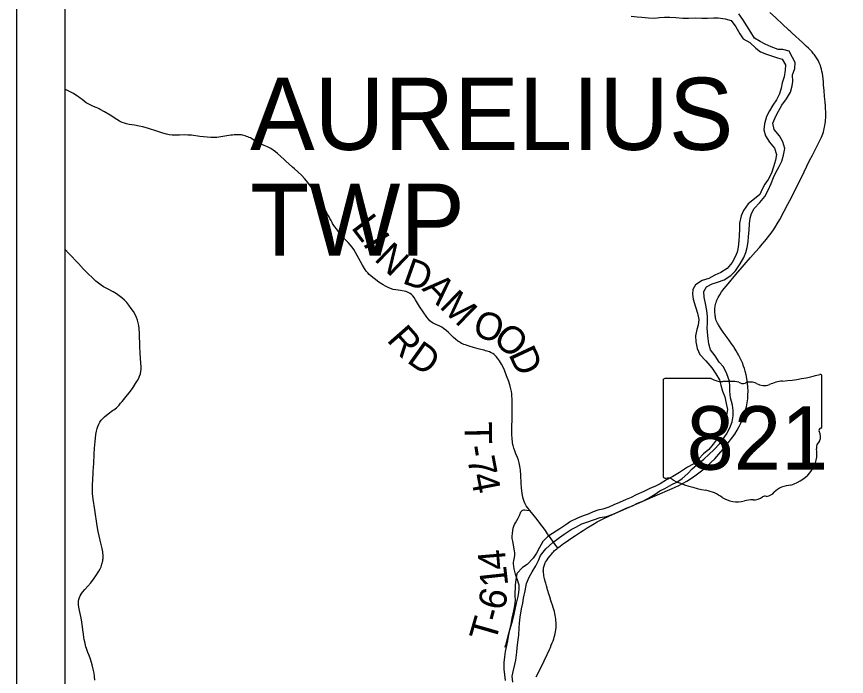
# Model space of a CAD drawing. Extents: x -10 to 158, y 8 to 33.
# Drawn here: x 126.004 to 127.727, y 27.363 to 28.734 of the extents above; entities that cross this region are included whole.
import ezdxf

# ---------------------------------------------------------------- set-up
doc = ezdxf.new("R2010")
doc.units = 0
for name, color, linetype in [('GM_X_Major_River', 7, 'Continuous'), ('GM_X_State_Location', 7, 'Continuous'), ('GM_X_State_Route', 7, 'Continuous'), ('GM_X_State_Shield', 7, 'Continuous'), ('GM_X_Township_Road', 7, 'Continuous'), ('GM_X_Township_Road_Text', 7, 'Continuous'), ('GM_X_Township_Text', 7, 'Continuous'), ('SH_Data', 7, 'Continuous')]:
    doc.layers.add(name, color=color, linetype=linetype)

msp = doc.modelspace()

# ---------------------------------------------------------------- linework, layer by layer
at = {"layer": 'GM_X_Major_River'}
for points in [[(127.2824, 27.7179), (127.293, 27.7233), (127.3043, 27.7277), (127.3156, 27.7339), (127.3295, 27.742), (127.3396, 27.7486), (127.3498, 27.7537), (127.3641, 27.7619), (127.375, 27.7669), (127.3859, 27.7743), (127.3979, 27.7851), (127.4069, 27.7947), (127.4196, 27.8055), (127.4305, 27.8147), (127.4413, 27.8243), (127.4526, 27.8347), (127.463, 27.8466), (127.4712, 27.857), (127.4779, 27.8666), (127.4846, 27.8799), (127.4893, 27.8921), (127.4914, 27.905), (127.4916, 27.916), (127.4904, 27.9267), (127.486, 27.9418), (127.485, 27.9562), (127.4845, 27.966), (127.484, 27.977), (127.4789, 27.9917), (127.4718, 28.0068), (127.4626, 28.0165), (127.4545, 28.0293), (127.4448, 28.0421), (127.4409, 28.0542), (127.4396, 28.0655), (127.4383, 28.0784), (127.4377, 28.0879), (127.4384, 28.0974), (127.4382, 28.111), (127.4369, 28.1239), (127.4344, 28.1379), (127.4316, 28.1511), (127.431, 28.1629), (127.4362, 28.1728), (127.4483, 28.179), (127.4592, 28.1822), (127.4732, 28.187), (127.4871, 28.1963), (127.4968, 28.2063), (127.5065, 28.2208), (127.5139, 28.2334), (127.5183, 28.2441), (127.5208, 28.2544), (127.5229, 28.2665), (127.5239, 28.2772), (127.5248, 28.2908), (127.5254, 28.3037), (127.5268, 28.3155), (127.5297, 28.325), (127.5356, 28.3357), (127.5472, 28.348), (127.5576, 28.3603), (127.5643, 28.3737), (127.5709, 28.3874), (127.5753, 28.3996), (127.5805, 28.4103), (127.5871, 28.4225), (127.5927, 28.4336), (127.5963, 28.4462), (127.5991, 28.4602), (127.5951, 28.4742), (127.5881, 28.4866), (127.5766, 28.4994), (127.5741, 28.513), (127.5804, 28.5271), (127.5856, 28.5378), (127.5926, 28.55), (127.6026, 28.5634), (127.6108, 28.5772), (127.614, 28.5901), (127.6158, 28.5996), (127.6149, 28.6133), (127.62, 28.6262), (127.6206, 28.6391), (127.6151, 28.6493), (127.6077, 28.6625), (127.5948, 28.6657), (127.5853, 28.6656), (127.5708, 28.6711), (127.5579, 28.677), (127.5479, 28.6822), (127.5357, 28.6896), (127.5283, 28.7016), (127.5202, 28.7151), (127.5121, 28.7279), (127.5036, 28.74)], [(127.4138, 28.7319), (127.4267, 28.7306), (127.4385, 28.7307), (127.451, 28.7317), (127.4608, 28.7318), (127.4749, 28.7293), (127.4878, 28.7257), (127.4971, 28.7129), (127.5056, 28.6986), (127.5126, 28.6877), (127.526, 28.68), (127.5387, 28.6684), (127.5486, 28.6609), (127.5612, 28.6558), (127.5711, 28.6525), (127.5837, 28.6485), (127.5932, 28.646), (127.6005, 28.6339), (127.5999, 28.6226), (127.5975, 28.6092), (127.5938, 28.5967), (127.5917, 28.5857), (127.5877, 28.5738), (127.5814, 28.5612), (127.574, 28.5501), (127.567, 28.5383), (127.5607, 28.5265), (127.5567, 28.5112), (127.5554, 28.4991), (127.5586, 28.4862), (127.5671, 28.4731), (127.5775, 28.4607), (127.5815, 28.4475), (127.5797, 28.4357), (127.5754, 28.422), (127.571, 28.409), (127.5644, 28.3957), (127.5573, 28.3861), (127.5514, 28.3739), (127.5473, 28.3643), (127.5327, 28.3528), (127.5226, 28.345), (127.5129, 28.3312), (127.5081, 28.3202), (127.5049, 28.3053), (127.5051, 28.2928), (127.5045, 28.2796), (127.5035, 28.2682), (127.5022, 28.2549), (127.4997, 28.2446), (127.496, 28.2351), (127.4897, 28.2232), (127.4793, 28.2106), (127.4661, 28.2024), (127.4537, 28.1969), (127.4413, 28.1903), (127.4273, 28.1856), (127.4138, 28.1771), (127.4079, 28.1671), (127.4072, 28.1573), (127.4089, 28.147), (127.4136, 28.1315), (127.4176, 28.118), (127.4201, 28.1047), (127.4187, 28.0933), (127.4162, 28.0838), (127.4133, 28.0709), (127.4139, 28.0584), (127.4171, 28.0447), (127.4226, 28.0323), (127.4353, 28.0188), (127.4476, 28.0042), (127.4557, 27.9918), (127.4631, 27.9794), (127.4659, 27.9684), (127.4695, 27.9563), (127.4742, 27.9439), (127.477, 27.9303), (127.4799, 27.9182), (127.4781, 27.9056), (127.4726, 27.893), (127.4664, 27.8789), (127.4605, 27.8637), (127.4561, 27.8541), (127.4501, 27.8458), (127.4413, 27.8348), (127.4303, 27.8256), (127.42, 27.8146), (127.4086, 27.8046), (127.3966, 27.7979), (127.3804, 27.7867), (127.3665, 27.779), (127.3533, 27.7716), (127.3402, 27.7638), (127.3304, 27.7587), (127.3187, 27.7537), (127.3059, 27.7478), (127.2901, 27.7404), (127.2799, 27.7353), (127.2693, 27.731), (127.2558, 27.7244)], [(127.2796, 28.735), (127.2925, 28.7337), (127.302, 28.7331), (127.3156, 28.7317), (127.3289, 28.7311), (127.3388, 28.732), (127.349, 28.7329), (127.3604, 28.7327), (127.3729, 28.7321), (127.3873, 28.7312), (127.3987, 28.7309), (127.4138, 28.7319)], [(127.2558, 27.7244), (127.2441, 27.72), (127.2335, 27.7153), (127.2211, 27.711), (127.2109, 27.709), (127.2007, 27.7054), (127.1909, 27.7007), (127.18, 27.6972), (127.1686, 27.6925), (127.1543, 27.6851), (127.1442, 27.6785), (127.1318, 27.67), (127.1168, 27.6603), (127.107, 27.6544), (127.0965, 27.6437), (127.0899, 27.6315), (127.0832, 27.6192), (127.0761, 27.6093), (127.0642, 27.5958), (127.0544, 27.5896), (127.0428, 27.577), (127.0407, 27.564), (127.0393, 27.5538), (127.0381, 27.531), (127.039, 27.5208), (127.038, 27.5109), (127.0355, 27.4999), (127.0319, 27.4847), (127.0302, 27.4721), (127.0274, 27.4599), (127.0245, 27.4466), (127.0231, 27.4371), (127.021, 27.4276), (127.0181, 27.4151), (127.0167, 27.4044), (127.0154, 27.3923), (127.0156, 27.3786), (127.0185, 27.3548)], [(127.0341, 27.3512), (127.0328, 27.3641), (127.0357, 27.3762), (127.0386, 27.388), (127.0403, 27.3975), (127.0428, 27.4135), (127.043, 27.423), (127.0444, 27.4348), (127.0465, 27.4488), (127.0474, 27.464), (127.048, 27.4739), (127.0497, 27.4868), (127.0522, 27.5039), (127.0547, 27.5157), (127.0564, 27.5263), (127.06, 27.5412), (127.0628, 27.5564), (127.0683, 27.5697), (127.0742, 27.5804), (127.082, 27.5934), (127.0872, 27.6041), (127.0916, 27.6144), (127.1028, 27.6286), (127.1174, 27.6417), (127.1309, 27.6517), (127.1407, 27.6587), (127.1553, 27.6684), (127.1651, 27.6738), (127.1772, 27.6801), (127.1877, 27.684), (127.2017, 27.6884), (127.2156, 27.6935), (127.2285, 27.6955), (127.2428, 27.7003), (127.2564, 27.7065), (127.2696, 27.7132), (127.2824, 27.7179)]]:
    msp.add_lwpolyline(points, dxfattribs=at)
at = {"layer": 'GM_X_State_Route'}
for points in [[(127.6133, 28.7005), (127.6098, 28.7037), (127.608, 28.7053), (127.6053, 28.7078), (127.5952, 28.7171), (127.5795, 28.732), (127.5676, 28.7429)], [(127.0828, 27.3622), (127.093, 27.3828), (127.1055, 27.4086), (127.1103, 27.4193), (127.1123, 27.4238), (127.114, 27.428), (127.1162, 27.4332), (127.1178, 27.4374), (127.1191, 27.4414), (127.1202, 27.445), (127.1212, 27.4488), (127.122, 27.4523), (127.1227, 27.4561), (127.1233, 27.4601), (127.1239, 27.4653), (127.1241, 27.4703), (127.124, 27.4753), (127.1238, 27.4787), (127.1235, 27.4826), (127.1228, 27.4866), (127.1221, 27.4906), (127.1214, 27.4942), (127.1204, 27.4982), (127.1192, 27.5027), (127.118, 27.5066), (127.1166, 27.5113), (127.1147, 27.5171), (127.1133, 27.5211), (127.1108, 27.5288), (127.1096, 27.5326), (127.1084, 27.5362), (127.1073, 27.5398), (127.1063, 27.5433), (127.1052, 27.547), (127.1039, 27.5513), (127.1031, 27.5544), (127.1024, 27.5572), (127.1016, 27.5608), (127.1008, 27.5638), (127.1002, 27.5664), (127.0996, 27.5691), (127.0989, 27.5728), (127.0983, 27.576), (127.0979, 27.5784), (127.0977, 27.5808), (127.0975, 27.5828), (127.0976, 27.5849), (127.0978, 27.5869), (127.098, 27.5887), (127.0984, 27.5908), (127.099, 27.5932), (127.0997, 27.5954), (127.1005, 27.5975), (127.1013, 27.5993), (127.1023, 27.6009), (127.1039, 27.6034), (127.1053, 27.6056), (127.1077, 27.6092), (127.1114, 27.6139), (127.115, 27.6183), (127.1168, 27.6203), (127.1187, 27.6224), (127.121, 27.6247), (127.1231, 27.6266), (127.1253, 27.6285), (127.1274, 27.6302), (127.1294, 27.6318), (127.1325, 27.6342), (127.136, 27.6368), (127.1396, 27.6393), (127.143, 27.6418), (127.1497, 27.6463), (127.1569, 27.6511), (127.1641, 27.6559), (127.175, 27.6632), (127.1801, 27.6666), (127.1889, 27.6724), (127.2, 27.6791), (127.2092, 27.6843), (127.2202, 27.69), (127.2348, 27.6969), (127.2586, 27.7074), (127.2934, 27.7226), (127.3298, 27.7385), (127.3652, 27.7538), (127.3776, 27.7596), (127.3876, 27.7647), (127.3952, 27.769), (127.4031, 27.774), (127.4119, 27.7799), (127.4205, 27.7861), (127.4288, 27.7927), (127.4373, 27.8), (127.4455, 27.8076), (127.4534, 27.8156), (127.4618, 27.8248), (127.4711, 27.8357), (127.4801, 27.8468), (127.4884, 27.8577), (127.4949, 27.8669), (127.4999, 27.8748), (127.5042, 27.8825), (127.5078, 27.8897), (127.511, 27.8972), (127.514, 27.9054), (127.5168, 27.9144), (127.5191, 27.9234), (127.5208, 27.932), (127.5219, 27.9401), (127.5225, 27.9482), (127.5227, 27.9563), (127.5223, 27.9644), (127.5215, 27.9731), (127.5201, 27.9824), (127.5187, 27.9898), (127.5167, 27.9977), (127.5151, 28.003), (127.5135, 28.0078), (127.5108, 28.0148), (127.5088, 28.0193), (127.5051, 28.0273), (127.5031, 28.0312), (127.501, 28.035), (127.4982, 28.0398), (127.494, 28.0464), (127.4928, 28.0484), (127.4889, 28.0538), (127.479, 28.0672), (127.4707, 28.0787), (127.4653, 28.087), (127.4631, 28.0904), (127.4611, 28.0937), (127.4603, 28.0954), (127.4593, 28.097), (127.4584, 28.0986), (127.4577, 28.1003), (127.4567, 28.1025), (127.4558, 28.1053), (127.4552, 28.1076), (127.4547, 28.1103), (127.4543, 28.1126), (127.454, 28.1152), (127.4536, 28.1196), (127.4535, 28.1223), (127.4535, 28.1249), (127.4537, 28.1282), (127.4541, 28.1309), (127.4545, 28.1336), (127.455, 28.136), (127.4557, 28.1385), (127.4564, 28.1405), (127.4573, 28.1429), (127.4581, 28.1451), (127.4607, 28.1506), (127.4638, 28.156), (127.4678, 28.1622), (127.4733, 28.1696), (127.4811, 28.1793), (127.4973, 28.1981), (127.5146, 28.2184), (127.5279, 28.234), (127.538, 28.2454), (127.5463, 28.2542), (127.552, 28.2612), (127.5566, 28.2667), (127.5606, 28.2717), (127.5645, 28.2765), (127.5686, 28.2816), (127.5719, 28.2862), (127.5753, 28.2914), (127.5782, 28.2955), (127.5832, 28.3034), (127.5884, 28.3126), (127.5978, 28.3301), (127.6053, 28.3444), (127.6132, 28.3599), (127.6391, 28.4116), (127.6505, 28.4349), (127.6562, 28.446), (127.6637, 28.4603), (127.6712, 28.4754), (127.6751, 28.4839), (127.6765, 28.4871), (127.6779, 28.4908), (127.679, 28.4942), (127.6802, 28.498), (127.6809, 28.5012), (127.6817, 28.5048), (127.6823, 28.5082), (127.683, 28.5123), (127.6833, 28.5156), (127.6836, 28.5196), (127.6838, 28.5237), (127.6839, 28.5278), (127.6839, 28.5324), (127.6839, 28.5371), (127.6836, 28.5424), (127.6833, 28.5483), (127.6827, 28.5573), (127.6817, 28.5681), (127.6808, 28.5805), (127.6795, 28.5922), (127.679, 28.5985), (127.6784, 28.6046), (127.6777, 28.6108), (127.6769, 28.6156), (127.676, 28.6205), (127.6751, 28.6248), (127.6739, 28.629), (127.6728, 28.6326), (127.6705, 28.6384), (127.6686, 28.6424), (127.6664, 28.6462), (127.6637, 28.6504), (127.6607, 28.6545), (127.6587, 28.6569), (127.6571, 28.6588), (127.6555, 28.6607), (127.6508, 28.6657), (127.6482, 28.6683), (127.6432, 28.673), (127.6354, 28.6801), (127.614, 28.6999), (127.6133, 28.7005)]]:
    msp.add_lwpolyline(points, dxfattribs=at)
at = {"layer": 'GM_X_State_Shield'}
for p, q in [((127.4463, 27.9824), (127.3498, 27.9824)), ((127.6761, 27.8826), (127.6761, 27.9873)), ((127.3465, 27.9789), (127.3465, 27.7788)), ((127.6761, 27.8827), (127.6761, 27.8826))]:
    msp.add_line(p, q, dxfattribs=at)
for centre, major_axis, start_param, end_param in [((127.3503, 27.9793), (0.00382, 0), 1.712693, 3.28349), ((127.4693, 28.0056), (0.037, 0), 4.042523, 4.731795), ((127.5587, 28.2552), (0.3495, 0), 4.814394, 5.042369), ((127.6725, 27.9878), (0.00367, 0), 6.141152, 7.989035), ((127.4816, 27.87), (0.133, 0), 1.404758, 1.657858), ((127.5117, 27.9804), (0.0107, 0), 3.836095, 5.185415), ((127.5274, 27.9573), (0.0222, 0), 0.950623, 2.079405), ((127.5561, 27.989), (0.0267, 0), 4.081561, 5.145723), ((127.6033, 27.9212), (0.0703, 0), 1.699011, 2.107814), ((127.6753, 27.875), (0.00568, 0), 1.883978, 3.671073), ((127.6722, 27.8822), (0.00393, 0), 5.05454, 6.418171), ((127.6391, 27.8617), (0.0341, 0), 5.934695, 6.695948), ((127.6893, 27.8388), (0.0248, 0), 2.387724, 3.262537), ((127.5783, 27.8255), (0.0874, 0), 5.101752, 6.440018), ((127.3503, 27.7784), (0.00385, 0), 3.00124, 4.508301), ((127.3509, 27.7988), (0.0294, 0), 4.665946, 4.897461), ((127.3569, 27.7673), (0.0106, 0), 0.519207, 1.627899), ((127.4908, 27.9471), (0.2524, 0), 4.195997, 4.488961), ((127.6152, 27.7226), (0.0479, 0), 1.647645, 2.488434), ((127.4155, 27.6889), (0.079, 0), 0.823519, 1.323587), ((127.5545, 27.7594), (0.0282, 0), 4.937069, 5.64225), ((127.5009, 27.7663), (0.0501, 0), 4.026481, 4.996735), ((127.5299, 27.6971), (0.0412, 0), 1.495662, 1.94098), ((127.5335, 27.7513), (0.0267, 0), 4.691044, 5.507374), ((127.5577, 27.7319), (0.00752, 0), 1.147584, 2.315152)]:
    msp.add_ellipse(centre, major_axis=major_axis, ratio=0.8, start_param=start_param, end_param=end_param, dxfattribs=at)
at = {"layer": 'GM_X_Township_Road'}
for points in [[(127.0697, 27.7083), (127.0673, 27.7108), (127.0646, 27.7141), (127.0621, 27.7177), (127.0596, 27.722), (127.0575, 27.7265), (127.0561, 27.7306), (127.0547, 27.736), (127.0534, 27.7434), (127.052, 27.7551), (127.0512, 27.7649), (127.0506, 27.7817), (127.0499, 27.7916), (127.0488, 27.8002), (127.0476, 27.8068), (127.0459, 27.8128), (127.0441, 27.8181), (127.0407, 27.826), (127.0381, 27.8323), (127.0363, 27.8375), (127.0355, 27.8403), (127.0349, 27.8429), (127.0344, 27.8452), (127.0338, 27.8484), (127.0333, 27.8519), (127.0329, 27.8558), (127.0326, 27.8599), (127.0324, 27.8639), (127.0323, 27.8696), (127.0321, 27.8757), (127.0326, 27.9042), (127.0327, 27.9222), (127.0325, 27.9378), (127.032, 27.9477), (127.0318, 27.9512), (127.0314, 27.955), (127.0308, 27.958), (127.0304, 27.9606), (127.0297, 27.9634), (127.0288, 27.9666), (127.0257, 27.9761), (127.0214, 27.9878), (127.0166, 27.9999), (127.0133, 28.0072), (127.0107, 28.0121), (127.0065, 28.019), (127.0026, 28.0246), (126.9999, 28.028), (126.9976, 28.0304), (126.9954, 28.0325), (126.9926, 28.0344), (126.9893, 28.0359), (126.9856, 28.0375), (126.9811, 28.0391), (126.9778, 28.04), (126.9746, 28.0409), (126.9711, 28.0419), (126.9676, 28.0428), (126.9625, 28.0441), (126.9523, 28.0468), (126.9433, 28.0493), (126.9392, 28.0506), (126.9357, 28.0519), (126.9326, 28.053), (126.9299, 28.0543), (126.9277, 28.0553), (126.925, 28.0569), (126.9226, 28.0583), (126.9203, 28.0599), (126.9153, 28.0637), (126.9107, 28.0678), (126.9005, 28.0778), (126.895, 28.0828), (126.8906, 28.0863), (126.8865, 28.089), (126.8827, 28.0911), (126.8729, 28.0952), (126.869, 28.0971), (126.8654, 28.0995), (126.8621, 28.1023), (126.8591, 28.1054), (126.8556, 28.1098), (126.8482, 28.1206), (126.8407, 28.132), (126.8324, 28.1458), (126.8293, 28.1505), (126.8266, 28.1539), (126.824, 28.1565), (126.8211, 28.1589), (126.8184, 28.1605), (126.8156, 28.1618), (126.8127, 28.1628), (126.8084, 28.1638), (126.801, 28.1648), (126.7912, 28.1663), (126.7857, 28.1674), (126.7804, 28.1691), (126.7752, 28.1712), (126.7697, 28.174), (126.765, 28.1767), (126.7561, 28.1826), (126.746, 28.1898), (126.74, 28.1946), (126.7361, 28.1981), (126.7329, 28.2015), (126.7296, 28.2056), (126.7264, 28.2105), (126.7219, 28.218), (126.7144, 28.2318), (126.7111, 28.2381), (126.7076, 28.2444), (126.7041, 28.2502), (126.7006, 28.2553), (126.6966, 28.26), (126.6928, 28.2641), (126.6886, 28.2686), (126.6849, 28.2727), (126.6817, 28.2763), (126.6783, 28.2804), (126.675, 28.2843), (126.6717, 28.2885), (126.67, 28.2907), (126.6679, 28.2935), (126.6649, 28.2975), (126.6628, 28.3004), (126.6601, 28.3046), (126.659, 28.3064), (126.6567, 28.3107), (126.6545, 28.3146), (126.6526, 28.3182), (126.6502, 28.3223), (126.6478, 28.3264), (126.6451, 28.3312), (126.6419, 28.3365), (126.6393, 28.3407), (126.6367, 28.3449), (126.6341, 28.3492), (126.6309, 28.3544), (126.6258, 28.3628), (126.6159, 28.3788), (126.6108, 28.3864), (126.6061, 28.3927), (126.6018, 28.3978), (126.5959, 28.4039), (126.5876, 28.4119), (126.5809, 28.4179), (126.5769, 28.4214), (126.5631, 28.4338), (126.5594, 28.4371), (126.5457, 28.4497), (126.5414, 28.4533), (126.5368, 28.4565), (126.5316, 28.4598), (126.525, 28.4633), (126.5178, 28.4666), (126.5131, 28.4687), (126.5092, 28.4706), (126.5054, 28.4724), (126.5021, 28.4743), (126.4946, 28.4789), (126.4919, 28.4806), (126.4892, 28.482), (126.4869, 28.483), (126.4841, 28.4842), (126.4812, 28.4853), (126.4783, 28.4863), (126.4754, 28.4871), (126.4728, 28.4877), (126.4706, 28.4882), (126.4676, 28.4886), (126.4648, 28.4888), (126.4617, 28.4888), (126.4588, 28.4888), (126.4555, 28.4885), (126.4522, 28.4881), (126.4487, 28.4877), (126.4279, 28.4843), (126.4239, 28.4836), (126.4199, 28.4833), (126.4166, 28.483), (126.4131, 28.4829), (126.4069, 28.4829), (126.3994, 28.4835), (126.3846, 28.4853), (126.3667, 28.4875), (126.3593, 28.488), (126.3525, 28.4882), (126.3419, 28.4878), (126.3332, 28.4877), (126.327, 28.488), (126.3209, 28.4888), (126.3148, 28.49), (126.3076, 28.4919), (126.2951, 28.4959), (126.278, 28.5015), (126.2661, 28.505), (126.2582, 28.5068), (126.2485, 28.5086), (126.2374, 28.5102), (126.2319, 28.5113), (126.2278, 28.5125), (126.2232, 28.5144), (126.2176, 28.5172), (126.2118, 28.5207), (126.198, 28.5292), (126.1863, 28.5363), (126.1777, 28.5412), (126.1755, 28.5424), (126.1728, 28.5439), (126.1694, 28.5454), (126.1637, 28.5477), (126.1596, 28.5494), (126.1551, 28.5514), (126.1513, 28.5534), (126.1481, 28.5552), (126.1441, 28.5581), (126.1398, 28.5617), (126.1359, 28.5647), (126.1325, 28.5673), (126.13, 28.5691), (126.1249, 28.5725), (126.122, 28.5741), (126.119, 28.5757), (126.1123, 28.5792), (126.1082, 28.5813), (126.104, 28.5836), (126.1038, 28.5837)], [(126.1628, 27.7848), (126.1631, 27.7889), (126.164, 27.8056), (126.1649, 27.8253), (126.1656, 27.8376), (126.1667, 27.8512), (126.1684, 27.866), (126.1695, 27.8727), (126.1708, 27.8781), (126.1723, 27.8828), (126.1743, 27.8873), (126.1767, 27.8916), (126.1796, 27.8956), (126.1824, 27.8988), (126.1864, 27.9026), (126.1938, 27.9088), (126.2032, 27.9156), (126.2058, 27.9174), (126.2087, 27.9196), (126.2111, 27.9217), (126.2139, 27.924), (126.2166, 27.9269), (126.2196, 27.9309), (126.2228, 27.9348), (126.2311, 27.9446), (126.2376, 27.9528), (126.2443, 27.9618), (126.2509, 27.9716), (126.2551, 27.9784), (126.2574, 27.9828), (126.2593, 27.9874), (126.2608, 27.9921), (126.2618, 27.9969), (126.2624, 28.0018), (126.2625, 28.0068), (126.2621, 28.0142), (126.2605, 28.0347), (126.2597, 28.0489), (126.259, 28.0756), (126.2583, 28.0862), (126.2575, 28.0923), (126.2564, 28.0978), (126.2548, 28.1032), (126.2526, 28.109), (126.2497, 28.1152), (126.2464, 28.1212), (126.242, 28.1279), (126.2372, 28.1344), (126.2325, 28.1402), (126.2277, 28.1451), (126.2226, 28.1496), (126.2167, 28.1542), (126.2111, 28.158), (126.2041, 28.1621), (126.1927, 28.1683), (126.1846, 28.1729), (126.1794, 28.1763), (126.1739, 28.1803), (126.1686, 28.1846), (126.1612, 28.1913), (126.1524, 28.2), (126.1485, 28.204), (126.1463, 28.2061), (126.1428, 28.2097), (126.1321, 28.221), (126.1121, 28.2422), (126.1038, 28.2507)], [(126.1666, 27.3554), (126.1658, 27.3634), (126.1648, 27.3702), (126.163, 27.3787), (126.1606, 27.3877), (126.157, 27.399), (126.1542, 27.407), (126.1519, 27.413), (126.1491, 27.4212), (126.1478, 27.425), (126.1469, 27.4284), (126.1459, 27.4321), (126.1452, 27.4355), (126.1444, 27.4399), (126.1437, 27.4441), (126.1428, 27.4509), (126.1416, 27.4601), (126.1408, 27.4661), (126.1402, 27.4712), (126.1394, 27.4761), (126.1386, 27.4809), (126.1373, 27.4877), (126.1359, 27.4943), (126.1344, 27.5004), (126.1328, 27.5076), (126.1322, 27.5119), (126.1321, 27.5162), (126.1324, 27.5199), (126.1331, 27.5235), (126.1342, 27.5271), (126.1356, 27.5305), (126.1377, 27.5343), (126.1406, 27.5383), (126.1454, 27.544), (126.1577, 27.5579), (126.1637, 27.5657), (126.1686, 27.5727), (126.1746, 27.582), (126.1773, 27.5868), (126.1793, 27.5913), (126.1803, 27.594), (126.1811, 27.5966), (126.1817, 27.5987), (126.1823, 27.6013), (126.1827, 27.6037), (126.183, 27.6062), (126.1833, 27.6086), (126.1834, 27.6111), (126.1834, 27.6137), (126.1834, 27.616), (126.1831, 27.6196), (126.1828, 27.6222), (126.1822, 27.6259), (126.1817, 27.6289), (126.179, 27.6403), (126.1752, 27.6553), (126.1731, 27.6643), (126.1709, 27.6765), (126.1661, 27.7096), (126.1629, 27.7316), (126.1617, 27.7433), (126.1614, 27.7513), (126.1615, 27.7599), (126.1621, 27.7735), (126.1628, 27.7848)], [(127.0176, 27.4241), (127.0189, 27.427), (127.0201, 27.4305), (127.0219, 27.4364), (127.0266, 27.4551), (127.032, 27.4743), (127.0369, 27.4929), (127.0421, 27.5153), (127.0451, 27.5293), (127.0465, 27.5379), (127.0473, 27.5446), (127.0474, 27.549), (127.0471, 27.5527), (127.0463, 27.557), (127.0449, 27.5618), (127.0412, 27.5716), (127.0398, 27.5758), (127.0383, 27.5811), (127.0369, 27.5872), (127.0361, 27.5921), (127.0358, 27.5965), (127.0359, 27.6002), (127.0363, 27.6039), (127.0376, 27.6106), (127.0384, 27.6155), (127.0385, 27.6186), (127.0383, 27.621), (127.0379, 27.6235), (127.0362, 27.6326), (127.0339, 27.6441), (127.0331, 27.6497), (127.033, 27.6546), (127.0332, 27.6602), (127.0339, 27.6664), (127.0348, 27.6713), (127.036, 27.6754), (127.0374, 27.6789), (127.0395, 27.6827), (127.0425, 27.6874), (127.0455, 27.6922), (127.0469, 27.6949), (127.0481, 27.6978), (127.0499, 27.7031), (127.0509, 27.7053), (127.052, 27.7068), (127.0534, 27.708), (127.0551, 27.7088), (127.0569, 27.7092), (127.0594, 27.7093), (127.0631, 27.7089), (127.0697, 27.7083)], [(127.1274, 27.6302), (127.1237, 27.6353), (127.1172, 27.6444), (127.1104, 27.654), (127.1064, 27.6595), (127.1018, 27.6662), (127.0953, 27.6752), (127.0823, 27.6927), (127.0697, 27.7083)]]:
    msp.add_lwpolyline(points, dxfattribs=at)
at = {"layer": 'GM_X_Township_Text'}
msp.add_lwpolyline([(126.1038, 30.3865), (126.1038, 27.0364), (126.3333, 27.0308), (126.5452, 27.0287), (127.0949, 27.0121), (127.9467, 26.9899), (128.0604, 26.987), (128.3868, 26.9847), (128.4032, 28.3535), (128.4042, 28.3758)], dxfattribs=at)
at = {"layer": 'SH_Data'}
for p, q in [((126.0038, 31.9623), (126.0038, 24.9623)), ((126.1038, 31.8623), (126.1038, 25.0623))]:
    msp.add_line(p, q, dxfattribs=at)

# ---------------------------------------------------------------- texts
at = {"layer": 'GM_X_State_Location'}
for s in ['s', 'r']:
    msp.add_text(s, height=0.000189, dxfattribs=at).set_placement((127.5076, 27.8656))
msp.add_text('821', height=0.000189, rotation=0, dxfattribs=at).set_placement((127.4408, 27.8518))
at = {"layer": 'GM_X_State_Shield'}
msp.add_text('821', height=0.13184, dxfattribs=at).set_placement((127.3951, 27.7929))
at = {"layer": 'GM_X_Township_Road_Text'}
for s, rotation, p in [('L', 307.3593, (126.6971, 28.2958)), ('I', 299.3169, (126.7217, 28.2638)), ('N', 316.4091, (126.7445, 28.2289)), ('D', 340.4044, (126.8027, 28.1809)), ('A', 314.1474, (126.844, 28.1678)), ('M', 315.7458, (126.8801, 28.1307)), ('O', 341.4323, (126.9478, 28.0733)), ('R', 311.4485, (126.7707, 28.0615)), ('O', 319.4864, (126.9902, 28.0602)), ('D', 324.5887, (126.812, 28.0172)), ('D', 295.0563, (127.0244, 28.0328)), ('T', 270.9901, (126.9338, 27.8921)), ('-', 279.2557, (126.9353, 27.8407)), ('7', 280.7533, (126.9394, 27.8161)), ('4', 280.9802, (126.946, 27.7814)), ('4', 94.6626, (127.0211, 27.5868)), ('1', 96.2779, (127.0248, 27.5527)), ('6', 77.2043, (127.016, 27.4984)), ('-', 75.2058, (127.0095, 27.4739)), ('T', 73.9521, (126.9975, 27.4319))]:
    msp.add_text(s, height=0.0568, rotation=rotation, dxfattribs=at).set_placement(p)
at = {"layer": 'GM_X_Township_Text'}
for s, p in [('AURELIUS', (126.4889, 28.4572)), ('TWP', (126.4889, 28.2372))]:
    msp.add_text(s, height=0.15, rotation=0, dxfattribs=at).set_placement(p)

doc.saveas('drawing.dxf')
